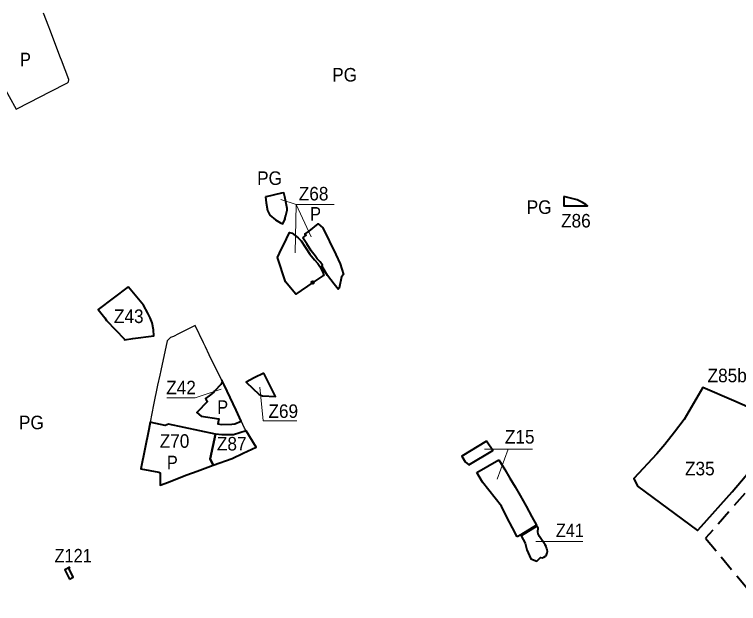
# Model space of a CAD drawing. Extents: x -650276 to -642489, y -1074311 to -1066658.
# Drawn here: x -647428 to -646145, y -1071743 to -1070699 of the extents above; entities that cross this region are included whole.
import ezdxf

# ---------------------------------------------------------------- set-up
doc = ezdxf.new("R2010")
doc.units = 0
doc.header["$LTSCALE"] = 9.6
doc.header["$PDMODE"] = 32
doc.header["$PDSIZE"] = 4.8
doc.linetypes.add('MEDIUM_DASHED', pattern=[4.5, 3, -1.5])
for name, color, linetype, lineweight in [('2', 7, 'Continuous', 40), ('3', 7, 'Continuous', 40), ('42', 7, 'Continuous', 25), ('44', 7, 'Continuous', 40), ('45', 7, 'Continuous', 40), ('46', 7, 'Continuous', 13), ('59', 7, 'Continuous', 13), ('60', 7, 'Continuous', 35), ('61', 7, 'MEDIUM_DASHED', 40)]:
    doc.layers.add(name, color=color, linetype=linetype, lineweight=lineweight)

msp = doc.modelspace()

# ---------------------------------------------------------------- linework, layer by layer
at = {"layer": '2'}
for points in [[(-647330.34, -1071678.82), (-647339.211, -1071683.431), (-647330.73, -1071700.09)], [(-647330.73, -1071700.09), (-647324.21, -1071696.2), (-647331.65, -1071681.7), (-647330.34, -1071678.82)]]:
    msp.add_lwpolyline(points, dxfattribs=at)
at = {"layer": '3'}
msp.add_lwpolyline([(-646921.668, -1071098.861), (-646920.54, -1071099.98), (-646904.64, -1071123.54), (-646896.62, -1071133.93), (-646890.59, -1071140.39), (-646887.07, -1071145.66), (-646881.97, -1071155.84), (-646879.91, -1071161.24), (-646881.68, -1071161.83), (-646899.85, -1071173.89), (-646929.64, -1071194.58), (-646948.286, -1071172.534), (-646962.471, -1071129.325), (-646955.138, -1071114.466), (-646951.831, -1071107.765), (-646951.831, -1071107.765), (-646940.67, -1071085.15), (-646940.67, -1071085.15), (-646936.51, -1071086.33), (-646925.88, -1071094.68)], close=True, dxfattribs=at)
at = {"layer": '42'}
msp.add_lwpolyline([(-647518.19, -1070693.93), (-647502.59, -1070724.13), (-647486.84, -1070754.54), (-647464.3, -1070795.6), (-647450.23, -1070821.25), (-647448.84, -1070823.79), (-647437.79, -1070844.12), (-647425.58, -1070866.7), (-647401.15, -1070854.25), (-647365.48, -1070835.85), (-647334.27, -1070819.86), (-647332.51, -1070817.97), (-647332.25, -1070813.72), (-647345.18, -1070779.89), (-647346.96, -1070775.41), (-647365.94, -1070725.08), (-647367.67, -1070720.73), (-647377.04, -1070696.22)], dxfattribs=at)
msp.add_lwpolyline([(-647187.85, -1071421.58), (-647190.4, -1071434.75), (-647204.42, -1071504.1), (-647172.74, -1071510.15), (-647170.01, -1071511.22), (-647170.18, -1071532.22), (-647170.23, -1071533.44), (-647155.58, -1071527.62), (-647151.28, -1071525.99), (-647123.17, -1071515.01), (-647104.47, -1071508.08), (-647076.46, -1071497.69), (-647042.78, -1071485.76), (-647022.81, -1071476.61), (-646999.77, -1071465.81), (-647017.7, -1071436.79), (-647020.52, -1071432.42), (-647030.23, -1071411.53), (-647035.47, -1071400.31), (-647056.48, -1071355.32), (-647073.98, -1071321.53), (-647083.22, -1071302), (-647090, -1071287.89), (-647093.39, -1071280.83), (-647108.16, -1071250.08), (-647130.76, -1071261.49), (-647137.84, -1071265.06), (-647146.3, -1071269.33), (-647152.09, -1071271.47), (-647157.83, -1071277.35), (-647168.91, -1071329.88), (-647170.63, -1071337.91), (-647174.73, -1071356.1), (-647181.75, -1071390.51)], close=True, dxfattribs=at)
at = {"layer": '44'}
msp.add_line((-647081.488, -1071486.251), (-647076.46, -1071497.69), dxfattribs=at)
msp.add_lwpolyline([(-646454.59, -1071021.54), (-646454.59, -1071038), (-646412.54, -1071038.01), (-646415.61, -1071035.4), (-646421.58, -1071031.81), (-646430.91, -1071027.44)], close=True, dxfattribs=at)
for points in [[(-647017.7, -1071436.79), (-647040.089, -1071443.76), (-647060.812, -1071444.006), (-647072.11, -1071442.6), (-647081.488, -1071486.251)], [(-647076.46, -1071497.69), (-647042.78, -1071485.76), (-647022.81, -1071476.61), (-646999.77, -1071465.81), (-647017.7, -1071436.79)]]:
    msp.add_lwpolyline(points, dxfattribs=at)
at = {"layer": '45'}
msp.add_line((-646609.21, -1071510.98), (-646570, -1071488.38), dxfattribs=at)
msp.add_line((-646609.21, -1071510.98), (-646570, -1071488.38), dxfattribs=at)
for points in [[(-646983.66, -1071022.3), (-646982.08, -1071032.76), (-646979.75, -1071046.19), (-646976.03, -1071054.29), (-646965.69, -1071063.05), (-646956.66, -1071067.91), (-646952.75, -1071069.62), (-646948.83, -1071061.12), (-646949.48, -1071060.79), (-646947.41, -1071054.95), (-646945.38, -1071045.82), (-646944.88, -1071042.78), (-646948.89, -1071024.84), (-646949.39, -1071021.83), (-646951.06, -1071014.78), (-646955.09, -1071015.67), (-646982.41, -1071022.23)], [(-646983.66, -1071022.3), (-646982.08, -1071032.76), (-646979.75, -1071046.19), (-646976.03, -1071054.29), (-646965.69, -1071063.05), (-646956.66, -1071067.91), (-646952.75, -1071069.62), (-646948.83, -1071061.12), (-646949.48, -1071060.79), (-646947.41, -1071054.95), (-646945.38, -1071045.82), (-646944.88, -1071042.78), (-646948.89, -1071024.84), (-646949.39, -1071021.83), (-646951.06, -1071014.78), (-646955.09, -1071015.67), (-646982.41, -1071022.23)], [(-646917.04, -1071094.75), (-646911.58, -1071089.9), (-646913.49, -1071088.22), (-646906.17, -1071082.72), (-646890.12, -1071069.67), (-646881.89, -1071077.03), (-646858.769, -1071124.46), (-646850.93, -1071140.54), (-646845.39, -1071159.98), (-646848.58, -1071163.95), (-646852.86, -1071183.98), (-646854.49, -1071185.87), (-646861.58, -1071177.05), (-646873.89, -1071161.58), (-646877.226, -1071155.611), (-646883.63, -1071144.15), (-646882.37, -1071143.39), (-646886.78, -1071137.25), (-646892.11, -1071131.81), (-646895.56, -1071126.84), (-646902.62, -1071117.58), (-646910.53, -1071105.18)], [(-646917.04, -1071094.75), (-646911.58, -1071089.9), (-646913.49, -1071088.22), (-646906.17, -1071082.72), (-646890.12, -1071069.67), (-646881.89, -1071077.03), (-646858.769, -1071124.46), (-646850.93, -1071140.54), (-646845.39, -1071159.98), (-646848.58, -1071163.95), (-646852.86, -1071183.98), (-646854.49, -1071185.87), (-646861.58, -1071177.05), (-646873.89, -1071161.58), (-646877.226, -1071155.611), (-646883.63, -1071144.15), (-646882.37, -1071143.39), (-646886.78, -1071137.25), (-646892.11, -1071131.81), (-646895.56, -1071126.84), (-646902.62, -1071117.58), (-646910.53, -1071105.18)], [(-647226.895, -1071181.511), (-647280.14, -1071221.92), (-647268.52, -1071236.78), (-647265.15, -1071241.1), (-647233.34, -1071274.07), (-647233.64, -1071275.42), (-647218.75, -1071273.32), (-647181.12, -1071268.66), (-647181.99, -1071257.66), (-647184.58, -1071245.67), (-647187.68, -1071236.74), (-647192.29, -1071228.1), (-647199.82, -1071213.98), (-647223.46, -1071185.83)], [(-647226.895, -1071181.511), (-647280.14, -1071221.92), (-647268.52, -1071236.78), (-647265.15, -1071241.1), (-647233.34, -1071274.07), (-647233.64, -1071275.42), (-647218.75, -1071273.32), (-647181.12, -1071268.66), (-647181.99, -1071257.66), (-647184.58, -1071245.67), (-647187.68, -1071236.74), (-647192.29, -1071228.1), (-647199.82, -1071213.98), (-647223.46, -1071185.83)], [(-646986.69, -1071334.53), (-647003.37, -1071342.99), (-647017.93, -1071350.33), (-646994.85, -1071372.49), (-646988.77, -1071374.77), (-646965.74, -1071376.18)], [(-646986.69, -1071334.53), (-647003.37, -1071342.99), (-647017.93, -1071350.33), (-646994.85, -1071372.49), (-646988.77, -1071374.77), (-646965.74, -1071376.18)], [(-647056.48, -1071355.32), (-647060.6, -1071346.87), (-647060.22, -1071349.87), (-647061.4, -1071352.51), (-647062.78, -1071354.77), (-647073.68, -1071366.75), (-647075.25, -1071368.01), (-647083.48, -1071374.62), (-647090.04, -1071379.44), (-647088.57, -1071381.97), (-647086.45, -1071384.59), (-647105.2, -1071404.54), (-647097.5, -1071410.96), (-647066.35, -1071415.79), (-647068.162, -1071424.298), (-647061.23, -1071425.434), (-647043.137, -1071424.978), (-647038.119, -1071424.37), (-647026.472, -1071419.614), (-647035.47, -1071400.31)], [(-647056.48, -1071355.32), (-647060.6, -1071346.87), (-647060.22, -1071349.87), (-647061.4, -1071352.51), (-647062.78, -1071354.77), (-647073.68, -1071366.75), (-647075.25, -1071368.01), (-647083.48, -1071374.62), (-647090.04, -1071379.44), (-647088.57, -1071381.97), (-647086.45, -1071384.59), (-647105.2, -1071404.54), (-647097.5, -1071410.96), (-647066.35, -1071415.79), (-647068.162, -1071424.298), (-647061.23, -1071425.434), (-647043.137, -1071424.978), (-647038.119, -1071424.37), (-647026.472, -1071419.614), (-647035.47, -1071400.31)], [(-646066.165, -1071422.155), (-646153.5, -1071383.85), (-646208.577, -1071360.044), (-646241.68, -1071416.887), (-646258.487, -1071439.265), (-646275.615, -1071460.886), (-646289.976, -1071477.514), (-646330.914, -1071521.11), (-646324, -1071535), (-646217.978, -1071613.552), (-646211.407, -1071606.247), (-646156.471, -1071545.166), (-646094.063, -1071471.007)], [(-646066.165, -1071422.155), (-646153.5, -1071383.85), (-646208.577, -1071360.044), (-646241.68, -1071416.887), (-646258.487, -1071439.265), (-646275.615, -1071460.886), (-646289.976, -1071477.514), (-646330.914, -1071521.11), (-646324, -1071535), (-646217.978, -1071613.552), (-646211.407, -1071606.247), (-646156.471, -1071545.166), (-646094.063, -1071471.007)], [(-647072.11, -1071442.6), (-647155.36, -1071425), (-647161.2, -1071427.33), (-647185.99, -1071421.98), (-647187.85, -1071421.58), (-647190.4, -1071434.75), (-647204.42, -1071504.1), (-647172.74, -1071510.15), (-647170.01, -1071511.22), (-647170.18, -1071532.22), (-647170.23, -1071533.44), (-647155.58, -1071527.62), (-647151.28, -1071525.99), (-647123.17, -1071515.01), (-647104.47, -1071508.08), (-647076.46, -1071497.69), (-647081.488, -1071486.251)], [(-647072.11, -1071442.6), (-647155.36, -1071425), (-647161.2, -1071427.33), (-647185.99, -1071421.98), (-647187.85, -1071421.58), (-647190.4, -1071434.75), (-647204.42, -1071504.1), (-647172.74, -1071510.15), (-647170.01, -1071511.22), (-647170.18, -1071532.22), (-647170.23, -1071533.44), (-647155.58, -1071527.62), (-647151.28, -1071525.99), (-647123.17, -1071515.01), (-647104.47, -1071508.08), (-647076.46, -1071497.69), (-647081.488, -1071486.251)], [(-646591.65, -1071454.91), (-646635.79, -1071481.6), (-646629.37, -1071491.74), (-646623.18, -1071496.99), (-646580.58, -1071471.48)], [(-646591.65, -1071454.91), (-646635.79, -1071481.6), (-646629.37, -1071491.74), (-646623.18, -1071496.99), (-646580.58, -1071471.48)], [(-646502.39, -1071605.72), (-646530.27, -1071622.79), (-646522.99, -1071636.22), (-646520.32, -1071647.59), (-646513.43, -1071663.64), (-646502.53, -1071667.82), (-646496.06, -1071661.5), (-646492.89, -1071661.75), (-646490.07, -1071660.88), (-646487.36, -1071659.1), (-646485.29, -1071656.53), (-646484.15, -1071653.38), (-646483.97, -1071650.63), (-646484.38, -1071647.41), (-646485.2, -1071644.85), (-646486.31, -1071641.97), (-646487.56, -1071639.23), (-646497.83, -1071624.02), (-646499.829, -1071620.704), (-646500.289, -1071619.291), (-646500.83, -1071615.62), (-646500.34, -1071609.66)], [(-646502.39, -1071605.72), (-646530.27, -1071622.79), (-646522.99, -1071636.22), (-646520.32, -1071647.59), (-646513.43, -1071663.64), (-646502.53, -1071667.82), (-646496.06, -1071661.5), (-646492.89, -1071661.75), (-646490.07, -1071660.88), (-646487.36, -1071659.1), (-646485.29, -1071656.53), (-646484.15, -1071653.38), (-646483.97, -1071650.63), (-646484.38, -1071647.41), (-646485.2, -1071644.85), (-646486.31, -1071641.97), (-646487.56, -1071639.23), (-646497.83, -1071624.02), (-646499.829, -1071620.704), (-646500.289, -1071619.291), (-646500.83, -1071615.62), (-646500.34, -1071609.66)]]:
    msp.add_lwpolyline(points, close=True, dxfattribs=at)
for points in [[(-646570, -1071488.38), (-646559.53, -1071505.12), (-646550.23, -1071520.88), (-646541.14, -1071536.3), (-646532.04, -1071551.72), (-646521.8, -1071570.34), (-646511.47, -1071589.11), (-646503.31, -1071603.95), (-646531.2, -1071621.07), (-646537.28, -1071624.8)], [(-646570, -1071488.38), (-646559.53, -1071505.12), (-646550.23, -1071520.88), (-646541.14, -1071536.3), (-646532.04, -1071551.72), (-646521.8, -1071570.34), (-646511.47, -1071589.11), (-646503.31, -1071603.95), (-646531.2, -1071621.07), (-646537.28, -1071624.8)], [(-646537.28, -1071624.8), (-646545.89, -1071609.07), (-646555.78, -1071589.66), (-646565.17, -1071570.4), (-646598.63, -1071527.8), (-646609.21, -1071510.98)], [(-646537.28, -1071624.8), (-646545.89, -1071609.07), (-646555.78, -1071589.66), (-646565.17, -1071570.4), (-646598.63, -1071527.8), (-646609.21, -1071510.98)]]:
    msp.add_lwpolyline(points, dxfattribs=at)
msp.add_point((-646899.85, -1071173.89), dxfattribs=at)
at = {"layer": '46'}
for p, q in [((-646510.087, -1071469.269), (-646595.257, -1071469.269)), ((-646510.087, -1071469.269), (-646595.257, -1071469.269)), ((-646421.181, -1071633.007), (-646504.11, -1071633.007)), ((-646421.181, -1071633.007), (-646504.11, -1071633.007))]:
    msp.add_line(p, q, dxfattribs=at)
for points in [[(-646928.092, -1071419.173), (-646987.822, -1071419.173), (-646993.397, -1071359.705)], [(-646928.092, -1071419.173), (-646987.822, -1071419.173), (-646993.397, -1071359.705)], [(-647158.414, -1071378.568), (-647108.186, -1071378.568), (-647061.975, -1071363.219)], [(-647158.414, -1071378.568), (-647108.186, -1071378.568), (-647061.975, -1071363.219)], [(-646510.087, -1071469.269), (-646553.419, -1071469.269), (-646572.844, -1071522.353)], [(-646510.087, -1071469.269), (-646553.419, -1071469.269), (-646572.844, -1071522.353)]]:
    msp.add_lwpolyline(points, dxfattribs=at)
at = {"layer": '59'}
for q in [(-646956.598, -1071026.547), (-646902.758, -1071092.681)]:
    msp.add_line((-646929.085, -1071035.693), q, dxfattribs=at)
msp.add_lwpolyline([(-646861.529, -1071035.693), (-646929.085, -1071035.693), (-646930.672, -1071121.165)], dxfattribs=at)
at = {"layer": '61'}
msp.add_lwpolyline([(-646044.948, -1071425.333), (-646077.593, -1071482.499), (-646203.387, -1071627.322), (-646107, -1071743)], dxfattribs=at)

# ---------------------------------------------------------------- texts
at = {"layer": '2', "width": 0.9}
msp.add_text('Z121', height=24, dxfattribs=at).set_placement((-647357.291, -1071670.187))
at = {"layer": '44', "width": 0.95}
for s, p in [('Z86', (-646459.658, -1071076.35)), ('Z86', (-646459.658, -1071076.35)), ('Z85b', (-646199.969, -1071350.698)), ('Z87', (-647069.618, -1071471.685)), ('Z87', (-647069.618, -1071471.685))]:
    msp.add_text(s, height=24, dxfattribs=at).set_placement(p)
at = {"layer": '46'}
for s, width, p in [('Z43', 0.95, (-647252.085, -1071245.723)), ('Z43', 0.95, (-647252.085, -1071245.723)), ('Z42', 0.95, (-647159.441, -1071372.08)), ('Z42', 0.95, (-647159.441, -1071372.08)), ('Z69', 0.95, (-646978.284, -1071413.97)), ('Z69', 0.95, (-646978.284, -1071413.97)), ('Z15', 0.95, (-646559.155, -1071459.428)), ('Z15', 0.95, (-646559.155, -1071459.428)), ('Z70', 0.95, (-647171.004, -1071466.914)), ('Z70', 0.95, (-647171.004, -1071466.914)), ('Z35', 0.95, (-646239.99, -1071515.768)), ('Z35', 0.95, (-646239.99, -1071515.768)), ('Z41', 0.9, (-646468.869, -1071625.297)), ('Z41', 0.9, (-646468.869, -1071625.297))]:
    msp.add_text(s, height=24, dxfattribs=dict(at, width=width)).set_placement(p)
at = {"layer": '59', "width": 0.95}
for s, p in [('PG', (-646998.384, -1071000.904)), ('Z68', (-646924.523, -1071028.411))]:
    msp.add_text(s, height=24, dxfattribs=at).set_placement(p)
at = {"layer": '60'}
for s, width, p in [('P', 0.9, (-647418.572, -1070790.564)), ('P', 0.9, (-647418.572, -1070790.564)), ('PG', 0.95, (-646865.3, -1070817.6)), ('PG', 0.95, (-646998.384, -1071000.904)), ('PG', 0.95, (-646520.539, -1071052.252)), ('PG', 0.95, (-646520.539, -1071052.252)), ('P', 0.9, (-646904.37, -1071064.222)), ('P', 0.9, (-647069.021, -1071406.74)), ('P', 0.9, (-647069.021, -1071406.74)), ('PG', 0.95, (-647420.449, -1071434.013)), ('PG', 0.95, (-647420.449, -1071434.013)), ('P', 0.9, (-647158.268, -1071504.971)), ('P', 0.9, (-647158.268, -1071504.971))]:
    msp.add_text(s, height=24, dxfattribs=dict(at, width=width)).set_placement(p)

doc.saveas('drawing.dxf')
